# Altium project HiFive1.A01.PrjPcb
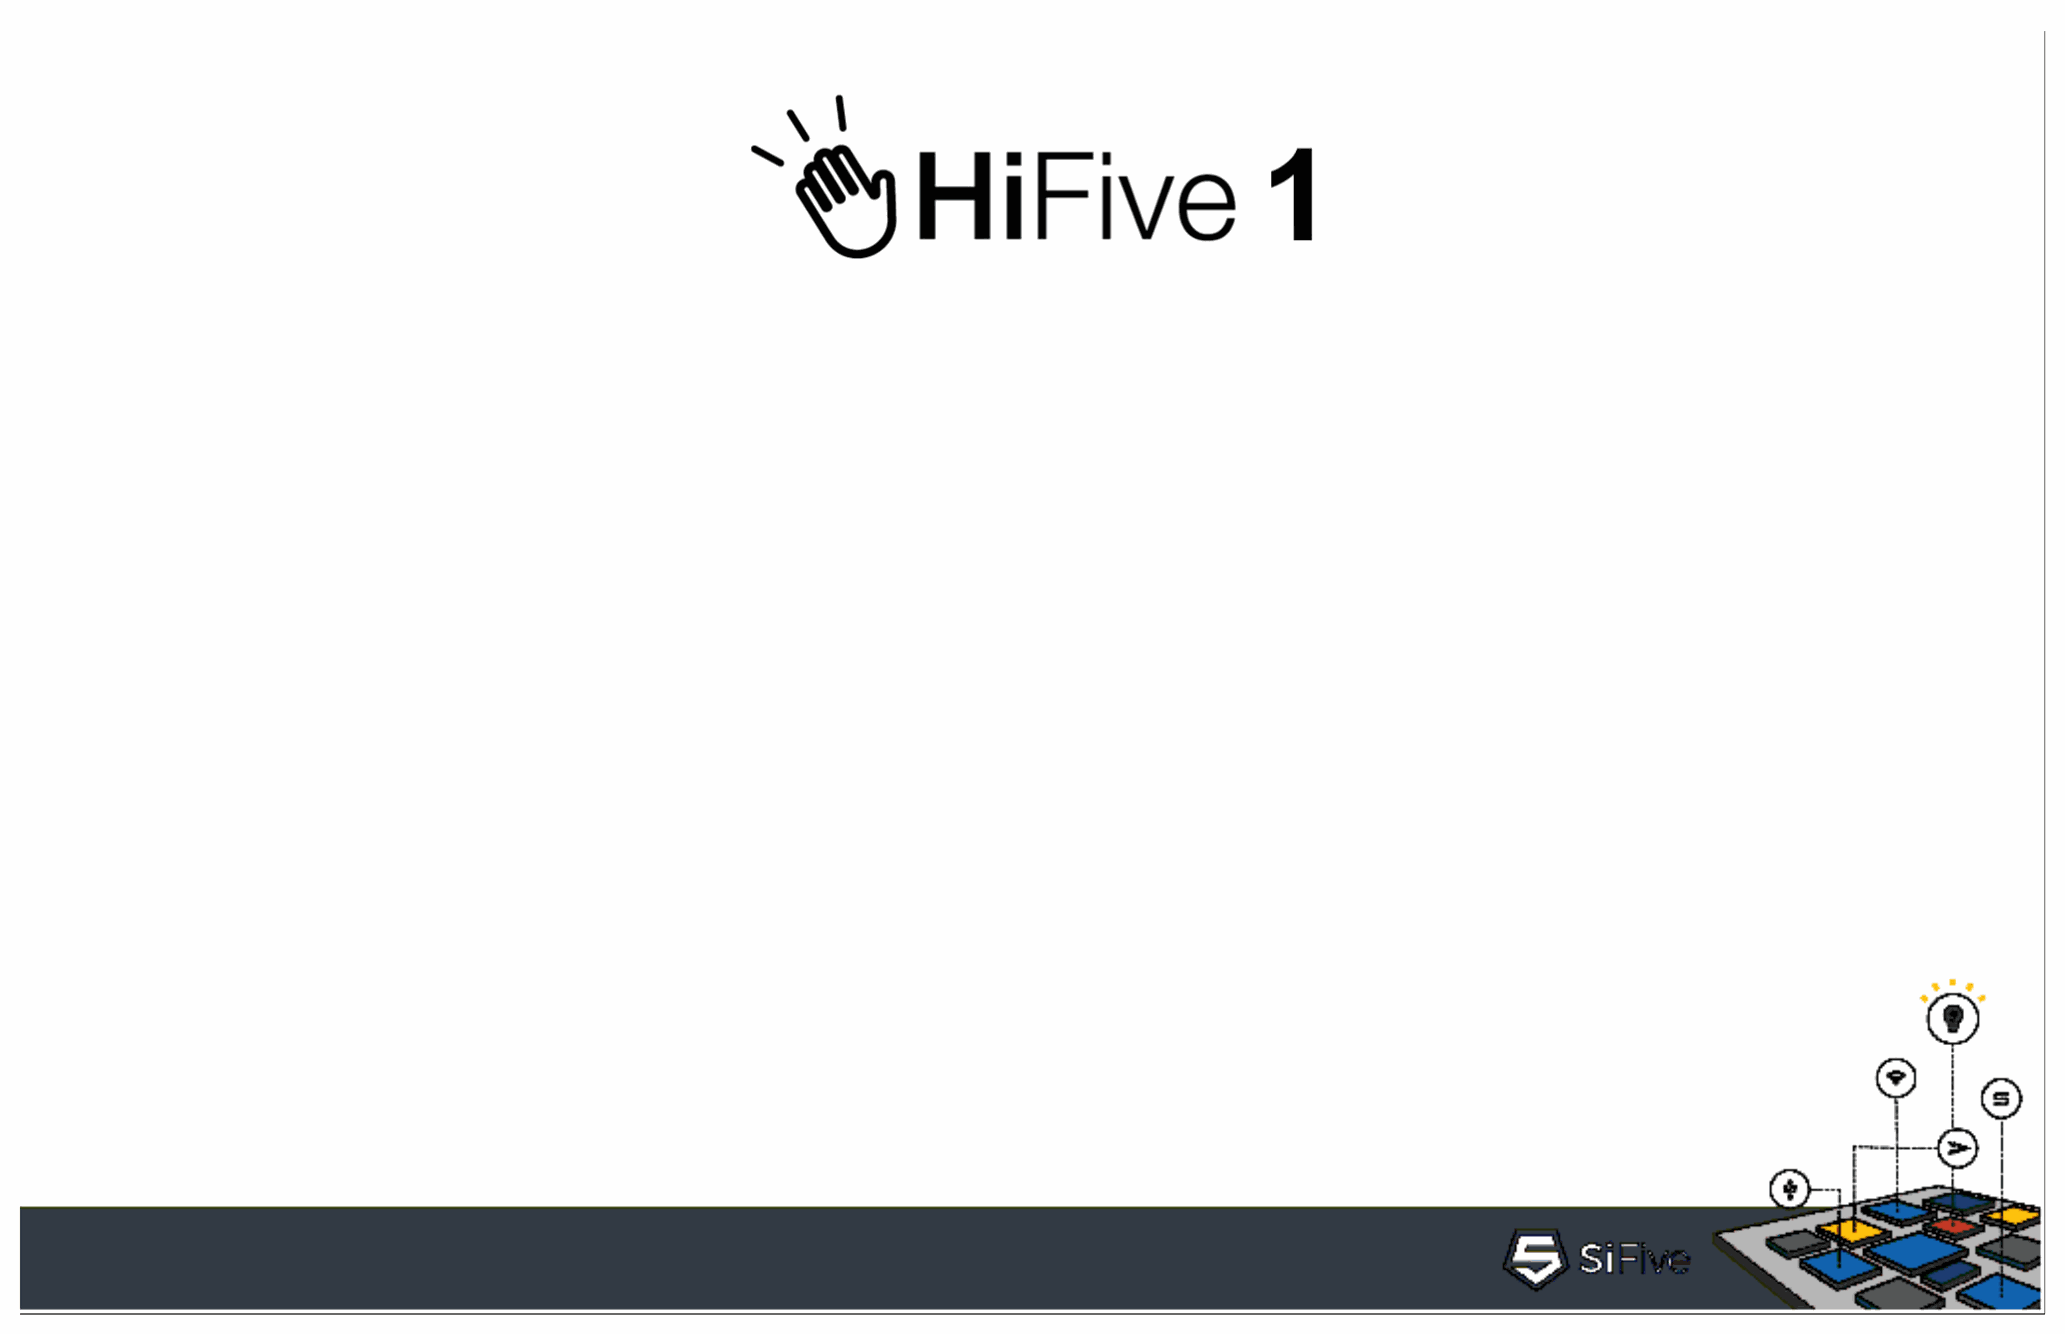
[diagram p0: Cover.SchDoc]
4 sheets, 123 parts. Net scope: flat (ports and power ports of the same name join across sheets).
Board file: HiFive1.A01.PcbDoc
Sheets:
  Cover.SchDoc
  Power.SchDoc
  Freedom_E310.SchDoc
  FT2232.SchDoc

## Sheet Cover.SchDoc
size B; SheetNumber: 1; SheetTotal: 4

## Sheet Power.SchDoc: Power Supply
size B; Revision: A01; SheetNumber: 2; SheetTotal: 4; ProjectCodeName: HiFive1
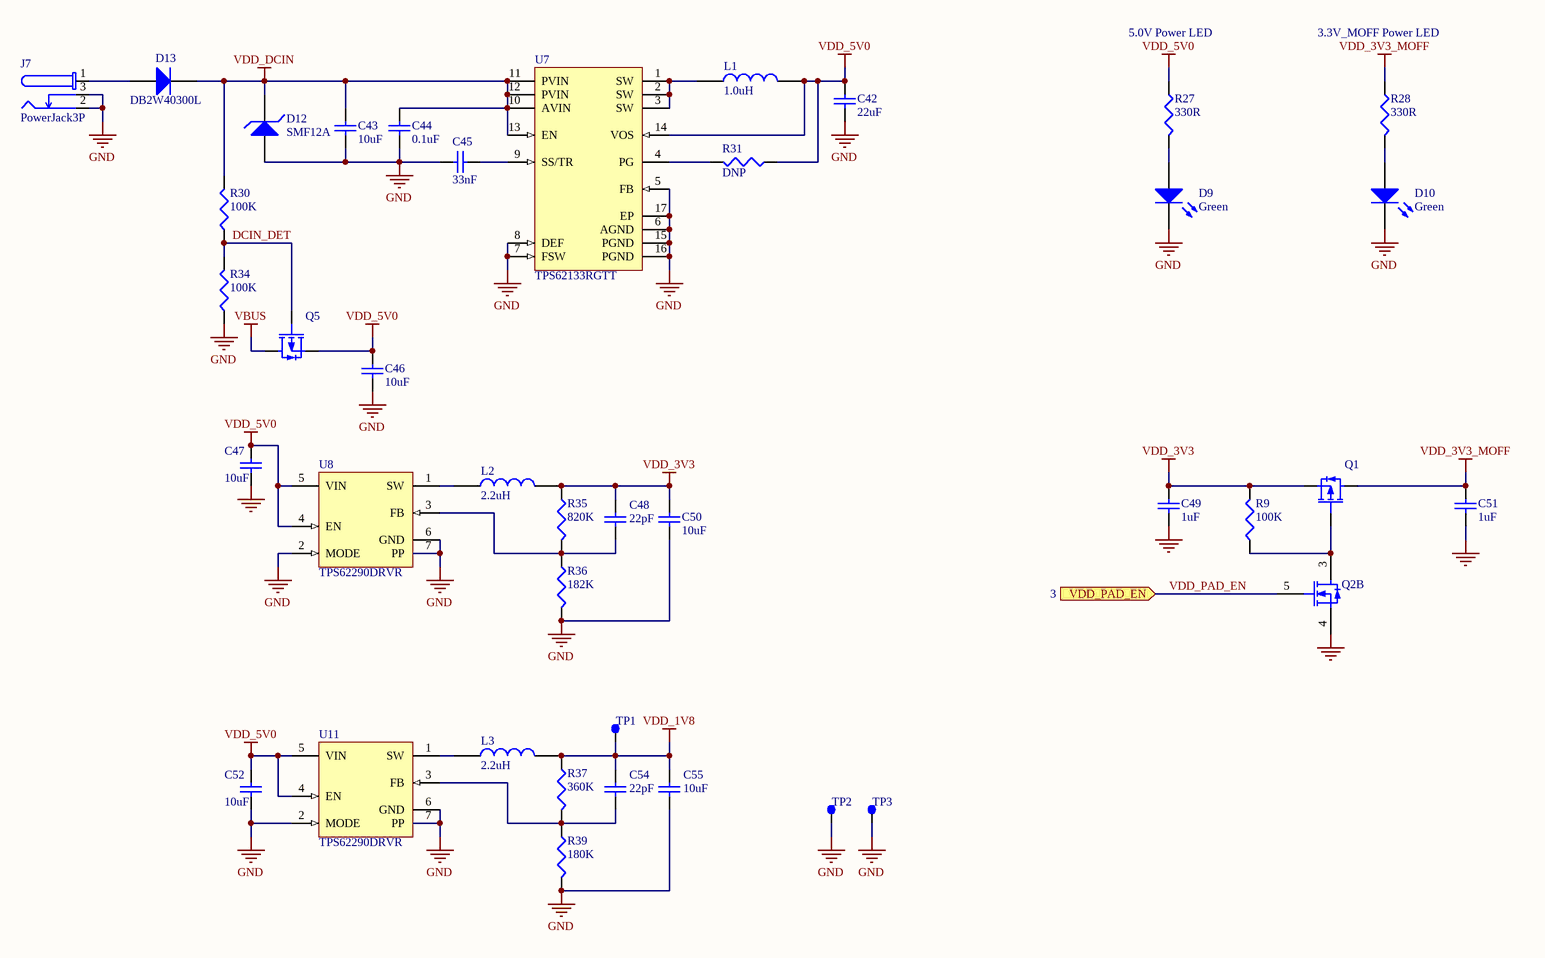
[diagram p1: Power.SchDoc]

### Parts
C42  22uF  [C0805]
C43  10uF  [C0805]
C44  0.1uF  [C0402]
C45  33nF  [C0402]
C46  10uF  [C0603]
C47  10uF  [C0603]
C48  22pF  [C0402]
C49  1uF  [C0603]
C50  10uF  [C0603]
C51  1uF  [C0603]
C52  10uF  [C0603]
C54  22pF  [C0402]
C55  10uF  [C0603]
D9  Green  [LED0805]
D10  Green  [LED0805]
D12  SMF12A  [SOD-123FL]
D13  DB2W40300L  [SOD-123FL]
J7  PowerJack3P  [PJ-102AH]
L1  1.0uH  [L252012]
L2  2.2uH  [L252012]
L3  2.2uH  [L252012]
Q1  MOSFET-P_SOT23  [SOT-23B]  (value not drawn)
Q2  DMN63D8LDW-7  [SC70-6]  (value not drawn)  (part B of 2)
Q5  MOSFET-P_SOT23  [SOT-23B]  (value not drawn)
R9  100K  [R0402]
R27  330R  [R0402]
R28  330R  [R0402]
R30  100K  [R0402]
R31  DNP  [R0402]  (no BOM)
R34  100K  [R0402]
R35  820K  [R0402]
R36  182K  [R0402]
R37  360K  [R0402]
R39  180K  [R0402]
TP1  Testpoint  [Testpoint_SMT]  (value not drawn)  (no BOM)
TP2  Testpoint  [Testpoint_SMT]  (value not drawn)  (no BOM)
TP3  Testpoint  [Testpoint_SMT]  (value not drawn)  (no BOM)
U7  TPS62133RGTT  [RGT16-1700X1700TP]
U8  TPS62290DRVR  [DRV6]
U11  TPS62290DRVR  [DRV6]

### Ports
VDD_PAD_EN (in, see 3)

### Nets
GND: C42.2 C43.2 C44.2 C45.2 C46.2 C47.2 C49.2 C50.2 C51.2 C52.2 C55.2 D9.1(K) D10.1(K) D12.2(A) J7.2 J7.3 Q2.4(S) R34.1 R36.2 R39.2 TP2.1 TP3.1 U7.5(FB) U7.6(AGND) U7.7(FSW) U7.8(DEF) U7.15(PGND) U7.16(PGND) U7.17(EP) U8.2(MODE) U8.6(GND) U8.7(PP) U11.2(MODE) U11.6(GND) U11.7(PP)
VBUS: Q5.3(D)
VDD_1V8: C54.1 C55.1 L3.2 R37.1 TP1.1
VDD_3V3: C48.1 C49.1 C50.1 L2.2 Q1.2(S) R9.2 R35.1
VDD_3V3_MOFF: C51.1 Q1.3(D) R28.1
VDD_5V0: C42.1 C46.1 C47.1 C52.1 L1.2 Q5.2(S) R27.1 R31.1 U7.14(VOS) U8.4(EN) U8.5(VIN) U11.4(EN) U11.5(VIN)
VDD_DCIN: C43.1 C44.1 D12.1(K) D13.1(K) R30.2 U7.10(AVIN) U7.11(PVIN) U7.12(PVIN) U7.13(EN)
DCIN_DET: Q5.1(G) R30.1 R34.2
VDD_PAD_EN: Q2.5(G) ; port VDD_PAD_EN
NetC45_1: C45.1 U7.9(SS/TR)
NetC48_2: C48.2 R35.2 R36.1 U8.3(FB)
NetC54_2: C54.2 R37.2 R39.1 U11.3(FB)
NetD9_2: D9.2(A) R27.2
NetD10_2: D10.2(A) R28.2
NetD13_2: D13.2(A) J7.1
NetL1_1: L1.1 U7.1(SW) U7.2(SW) U7.3(SW)
NetL2_1: L2.1 U8.1(SW)
NetL3_1: L3.1 U11.1(SW)
NetQ1_1: Q1.1(G) Q2.3(D) R9.1
NetR31_2: R31.2 U7.4(PG)

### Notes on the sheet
- 5.0V Power LED
- 3.3V_MOFF Power LED

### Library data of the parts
C42 = C0100010: 22µF 6.3V Ceramic Capacitor X5R 0805; Manufacturer: Murata Electronics; Manufacturer PN: GRM21BR60J226ME39L
C43 = C0100015: 10µF ±10% 25V Ceramic Capacitor X5R 0805; Manufacturer: Murata Electronics; Manufacturer PN: GRM21BR61E106KA73L
C44 = C0100004: 0.10µF 16V Ceramic Capacitor X7R 0402; Manufacturer: Murata Electronics; Manufacturer PN: GRM155R71C104KA88J
C45 = C0100011: 33nF 25V Ceramic Capacitor X7R 0402; Manufacturer: Murata Electronics; Manufacturer PN: GRM155R71E333KA88D
C46 C47 C50 C52 C55 = C0100007: 10µF 6.3V Ceramic Capacitor X5R 0603; Manufacturer: Murata Electronics; Manufacturer PN: GRM188R60J106ME47J
C48 C54 = C0100009: 22pF 50V Ceramic Capacitor C0G, NP0 0402; Manufacturer: Murata Electronics; Manufacturer PN: GRM1555C1H220JA01J
C49 C51 = C0100006: 1µF 16V Ceramic Capacitor X5R 0603; Manufacturer: Murata Electronics; Manufacturer PN: GRM188R61C105KA93D
D9 D10 = E0000001: Green 570nm LED Indication - Discrete 2.2V 0805; Manufacturer: OSRAM Opto Semiconductors Inc; Manufacturer PN: LG R971-KN-1
D12 = D0000002: TVS DIODE 12VWM 19.9VC SOD123; Manufacturer: Littelfuse Inc
D13 = D0000006: Diode Schottky 40V 3A (DC) Surface Mount; Manufacturer: Panasonic Electronic Components
J7 = J0000003: Power Barrel Connector Jack 2.00mm ID (0.079"), 5.50mm OD (0.217") Through Hole, Right Angle; Manufacturer: CUI Inc
L1 = L0000003: 1µH Shielded Inductor 3.3A 40 mOhm; Manufacturer: Murata Electronics; Manufacturer PN: DFE252012F-1R0M=P2
L2 L3 = L0000002: 2.2µH Shielded Wirewound Inductor 3A 84 mOhm; Manufacturer: Murata Electronics; Manufacturer PN: DFE252012P-2R2M=P2
Q1 Q5 = Q0000002: MOSFET P-CH 20V 3.7A SOT-23; Manufacturer: Infineon Technologies; Manufacturer PN: IRLML6402TRPBF; Value: P-Channel
Q2 = Q0000003: MOSFET 2N-CH 30V 0.22A SOT363; Manufacturer: Diodes Inc
R9 R30 R31 R34 = R0000012: RES SMD 100K OHM 1% 1/16W 0402; Manufacturer: Yageo; Manufacturer PN: RC0402FR-07100KL
R27 R28 = R0000026: RES SMD 330 OHM 1% 1/16W 0402; Manufacturer: Yageo; Manufacturer PN: RC0402FR-07330RL
R35 = R0000017: RES SMD 820K OHM 1% 1/16W 0402; Manufacturer: Yageo; Manufacturer PN: RC0402FR-07820KL
R36 = R0000018: RES SMD 182K OHM 1% 1/16W 0402; Manufacturer: Yageo; Manufacturer PN: RC0402FR-07182KL
R37 = R0000015: RES SMD 360K OHM 1% 1/16W 0402; Manufacturer: Yageo; Manufacturer PN: RC0402FR-07360KL
R39 = R0000014: RES SMD 180K OHM 1% 1/16W 0402; Manufacturer: Yageo; Manufacturer PN: RC0402FR-07180KL
TP1-TP3 = M0000002: Test Point SMT
U7 = U0000007: Buck Switching Regulator IC Positive Fixed 5V 1 Output 3A 16-VFQFN Exposed Pad; Manufacturer: Texas Instruments
U8 U11 = U0000006: Buck Switching Regulator IC Positive Adjustable 0.6V 1 Output 1A 6-WDFN Exposed Pad; Manufacturer: Texas Instruments

## Sheet Freedom_E310.SchDoc: Freedom E310
size B; Revision: A01; SheetNumber: 3; SheetTotal: 4; ProjectCodeName: HiFive1
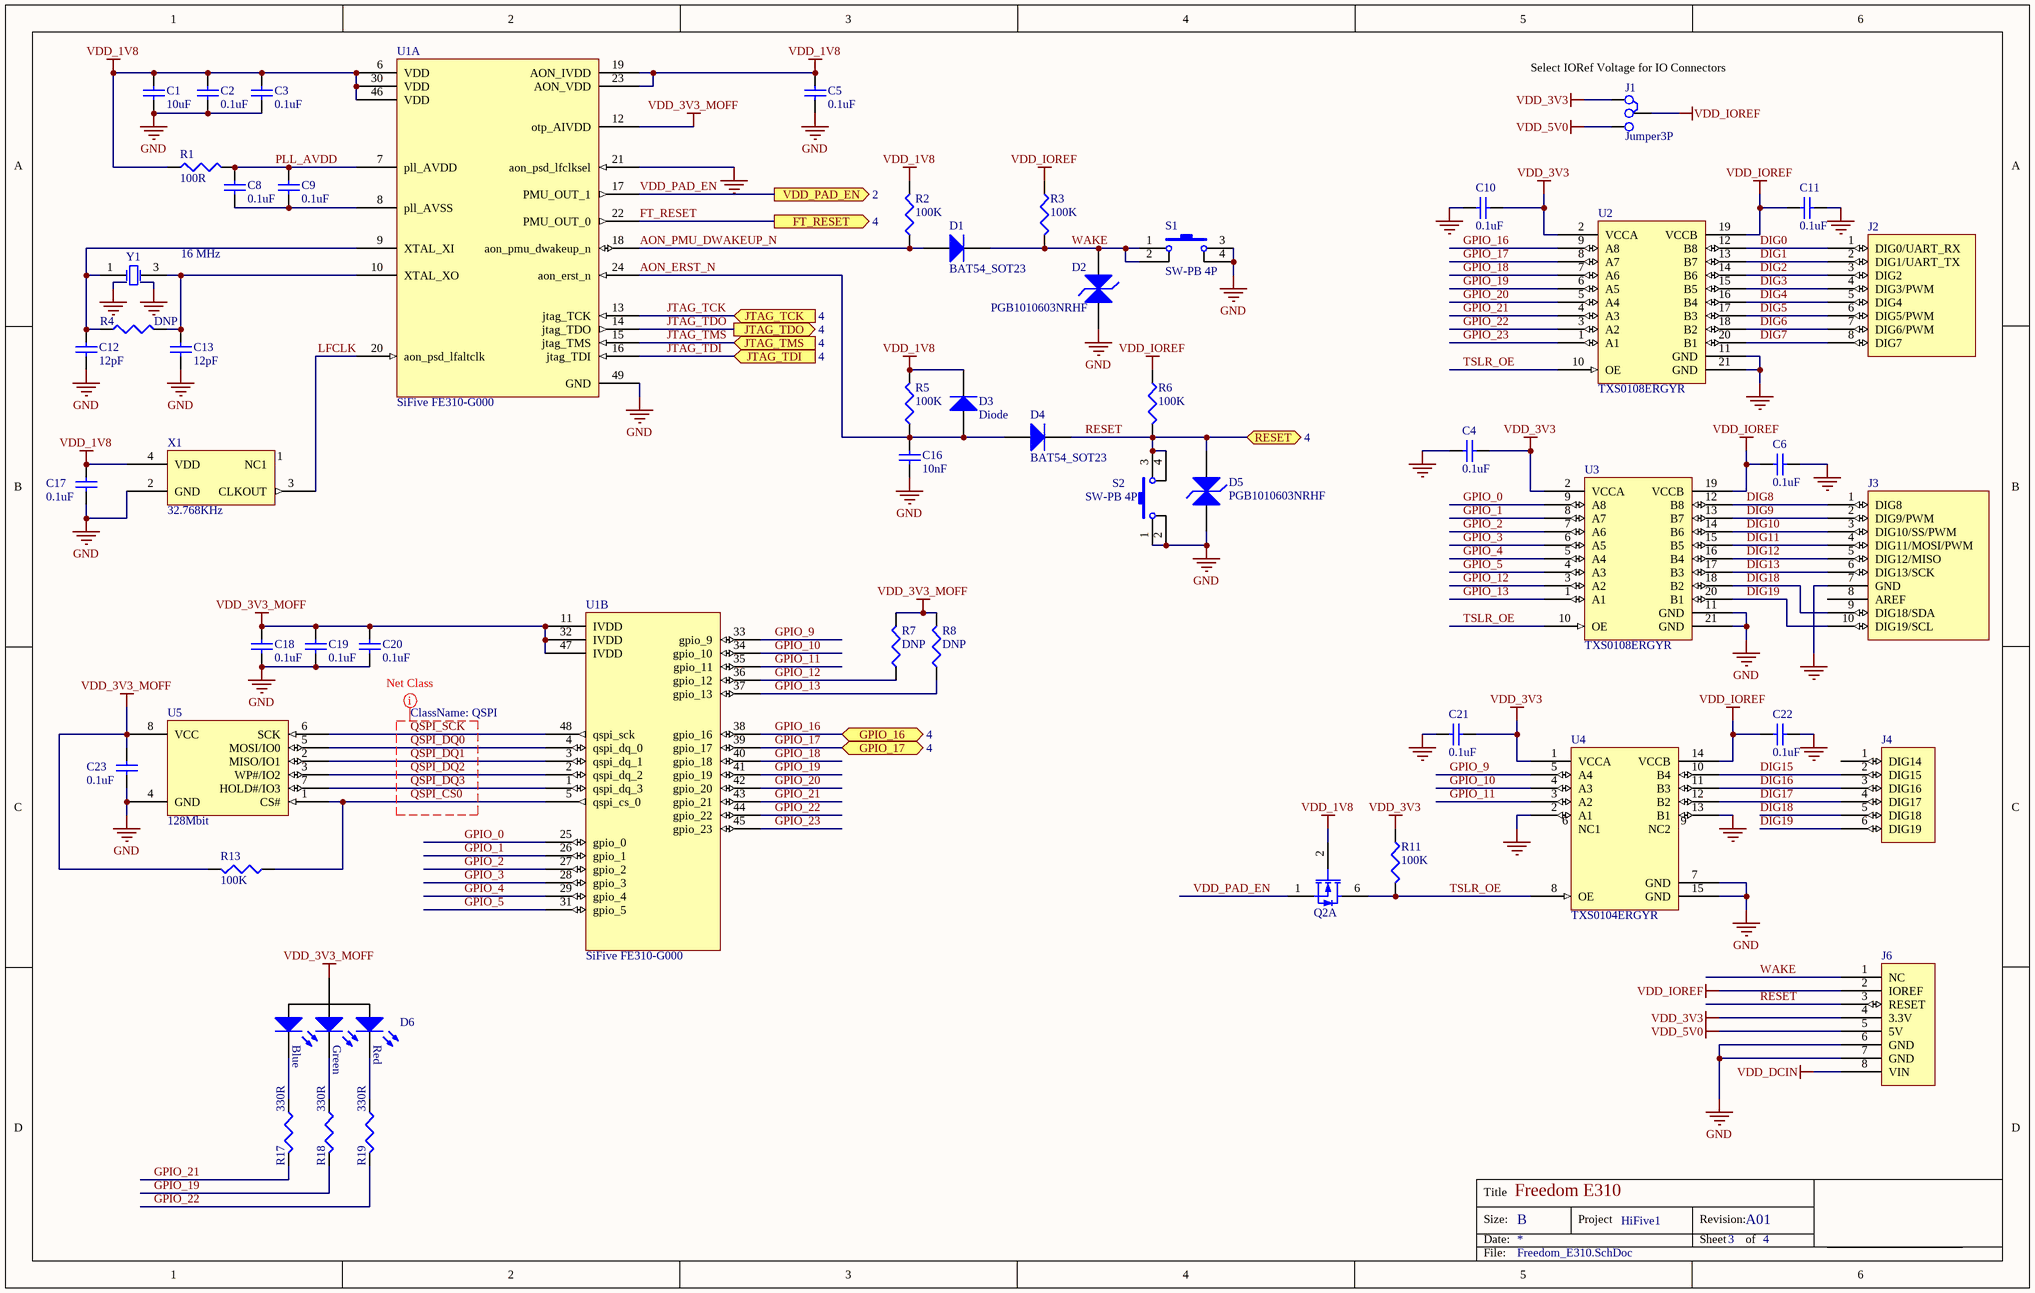
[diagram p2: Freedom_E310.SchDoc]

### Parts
C1  10uF  [C0603]
C2  0.1uF  [C0402]
C3  0.1uF  [C0402]
C4  0.1uF  [C0402]
C5  0.1uF  [C0402]
C6  0.1uF  [C0402]
C8  0.1uF  [C0402]
C9  0.1uF  [C0402]
C10  0.1uF  [C0402]
C11  0.1uF  [C0402]
C12  12pF  [C0402]
C13  12pF  [C0402]
C16  10nF  [C0402]
C17  0.1uF  [C0402]
C18  0.1uF  [C0402]
C19  0.1uF  [C0402]
C20  0.1uF  [C0402]
C21  0.1uF  [C0402]
C22  0.1uF  [C0402]
C23  0.1uF  [C0402]
D1  BAT54_SOT23  [SOT-23B]
D2  PGB1010603NRHF  [R0603]
D3  Diode  [SOD523]
D4  BAT54_SOT23  [SOT-23B]
D5  PGB1010603NRHF  [R0603]
D6  LED_RGB_LTST-C19HE1WT  [LED0606]  (value not drawn)
J1  Jumper3P  [Header_2.54mm_3p]
J2  8P_IO  [8P_IO]  (value not drawn)
J3  10P  [10P]  (value not drawn)
J4  6P  [6P]  (value not drawn)
J6  POWER  [8P_POWER]  (value not drawn)
Q2  DMN63D8LDW-7  [SC70-6]  (value not drawn)  (part A of 2)
R1  100R  [R0402]
R2  100K  [R0402]
R3  100K  [R0402]
R4  DNP  [R0402]  (no BOM)
R5  100K  [R0402]
R6  100K  [R0402]
R7  DNP  [R0402]  (no BOM)
R8  DNP  [R0402]  (no BOM)
R11  100K  [R0402]
R13  100K  [R0402]
R17  330R  [R0402]
R18  330R  [R0402]
R19  330R  [R0402]
S1  SW-PB 4P  [PTS645_SMT]
S2  SW-PB 4P  [PTS645_SMT]
U1  SiFive FE310-G000  [QFN48_40P600X600X90_HS-49]  (parts A,B of 2)
U2  TXS0108ERGYR  [RGY-20]
U3  TXS0108ERGYR  [RGY-20]
U4  TXS0104ERGYR  [RGY-14]
U5  128Mbit  [SOIC127P790X216-8N]
X1  32.768KHz  [SiTime2012]
Y1  16 MHz  [X3225]

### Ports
FT_RESET (out, see 4), GPIO_16 (bidir, see 4), GPIO_17 (bidir, see 4), JTAG_TCK (in, see 4), JTAG_TDI (in, see 4), JTAG_TDO (out, see 4), JTAG_TMS (in, see 4), RESET (bidir, see 4), VDD_PAD_EN (out, see 2)

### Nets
GND: C1.2 C2.2 C3.2 C4.2 C5.2 C6.2 C10.2 C11.2 C12.2 C13.2 C16.2 C17.2 C18.2 C19.2 C20.2 C21.2 C22.2 C23.2 D2.2 D5.2 J3.7(GND) J6.6(GND) J6.7(GND) S1.3 S1.4 S2.1 S2.2 U1.21(aon_psd_lfclksel) U1.49(GND) U2.11(GND) U2.21(GND) U3.11(GND) U3.21(GND) U4.2(A1) U4.7(GND) U4.13(B1) U4.15(GND) U5.4(GND) X1.2(GND) Y1.2(NC1) Y1.4(NC2)
VDD_1V8: C1.1 C2.1 C3.1 C5.1 C17.1 D3.1(K) Q2.2(G) R1.1 R2.2 R5.2 U1.6(VDD) U1.19(AON_IVDD) U1.23(AON_VDD) U1.30(VDD) U1.46(VDD) X1.4(VDD)
VDD_3V3: C4.1 C10.1 C21.1 J1.1(C1) J6.4(3.3V) R11.1 U2.2(VCCA) U3.2(VCCA) U4.1(VCCA)
VDD_3V3_MOFF: C18.1 C19.1 C20.1 C23.1 D6.4(A) R7.2 R8.2 R13.2 U1.11(IVDD) U1.12(otp_AIVDD) U1.32(IVDD) U1.47(IVDD) U5.8(VCC)
VDD_5V0: J1.3(C3) J6.5(5V)
VDD_DCIN: J6.8(VIN)
VDD_IOREF: C6.1 C11.1 C22.1 J1.2(C2) J6.2(IOREF) R3.1 R6.1 U2.19(VCCB) U3.19(VCCB) U4.14(VCCB)
AON_ERST_N: C16.1 D3.2(A) D4.1(A) R5.1 U1.24(aon_erst_n)
AON_PMU_DWAKEUP_N: D1.1(A) R2.1 U1.18(aon_pmu_dwakeup_n)
DIG0: J2.1(DIG0/UART_RX) U2.12(B8)
DIG1: J2.2(DIG1/UART_TX) U2.13(B7)
DIG2: J2.3(DIG2) U2.14(B6)
DIG3: J2.4(DIG3/PWM) U2.15(B5)
DIG4: J2.5(DIG4) U2.16(B4)
DIG5: J2.6(DIG5/PWM) U2.17(B3)
DIG6: J2.7(DIG6/PWM) U2.18(B2)
DIG7: J2.8(DIG7) U2.20(B1)
DIG8: J3.1(DIG8) U3.12(B8)
DIG9: J3.2(DIG9/PWM) U3.13(B7)
DIG10: J3.3(DIG10/SS/PWM) U3.14(B6)
DIG11: J3.4(DIG11/MOSI/PWM) U3.15(B5)
DIG12: J3.5(DIG12/MISO) U3.16(B4)
DIG13: J3.6(DIG13/SCK) U3.17(B3)
DIG15: J4.2(DIG15) U4.10(B4)
DIG16: J4.3(DIG16) U4.11(B3)
DIG17: J4.4(DIG17) U4.12(B2)
DIG18: J3.9(DIG18/SDA) J4.5(DIG18) U3.18(B2)
DIG19: J3.10(DIG19/SCL) J4.6(DIG19) U3.20(B1)
FT_RESET: U1.22(PMU_OUT_0) ; port FT_RESET
GPIO_0: U1.25(gpio_0) U3.9(A8)
GPIO_1: U1.26(gpio_1) U3.8(A7)
GPIO_2: U1.27(gpio_2) U3.7(A6)
GPIO_3: U1.28(gpio_3) U3.6(A5)
GPIO_4: U1.29(gpio_4) U3.5(A4)
GPIO_5: U1.31(gpio_5) U3.4(A3)
GPIO_9: U1.33(gpio_9) U4.5(A4)
GPIO_10: U1.34(gpio_10) U4.4(A3)
GPIO_11: U1.35(gpio_11) U4.3(A2)
GPIO_12: R7.1 U1.36(gpio_12) U3.3(A2)
GPIO_13: R8.1 U1.37(gpio_13) U3.1(A1)
GPIO_16: U1.38(gpio_16) U2.9(A8) ; port GPIO_16
GPIO_17: U1.39(gpio_17) U2.8(A7) ; port GPIO_17
GPIO_18: U1.40(gpio_18) U2.7(A6)
GPIO_19: R18.2 U1.41(gpio_19) U2.6(A5)
GPIO_20: U1.42(gpio_20) U2.5(A4)
GPIO_21: R17.2 U1.43(gpio_21) U2.4(A3)
GPIO_22: R19.2 U1.44(gpio_22) U2.3(A2)
GPIO_23: U1.45(gpio_23) U2.1(A1)
JTAG_TCK: U1.13(jtag_TCK) ; port JTAG_TCK
JTAG_TDI: U1.16(jtag_TDI) ; port JTAG_TDI
JTAG_TDO: U1.14(jtag_TDO) ; port JTAG_TDO
JTAG_TMS: U1.15(jtag_TMS) ; port JTAG_TMS
LFCLK: U1.20(aon_psd_lfaltclk) X1.3(CLKOUT)
PLL_AVDD: C8.1 C9.1 R1.2 U1.7(pll_AVDD)
QSPI_CS0: R13.1 U1.5(qspi_cs_0) U5.1(CS#)
QSPI_DQ0: U1.4(qspi_dq_0) U5.5(MOSI/IO0)
QSPI_DQ1: U1.3(qspi_dq_1) U5.2(MISO/IO1)
QSPI_DQ2: U1.2(qspi_dq_2) U5.3(WP#/IO2)
QSPI_DQ3: U1.1(qspi_dq_3) U5.7(HOLD#/IO3)
QSPI_SCK: U1.48(qspi_sck) U5.6(SCK)
RESET: D4.3(K) D5.1 J6.3(RESET) R6.2 S2.3 S2.4 ; port RESET
TSLR_OE: Q2.6(D) R11.2 U2.10(OE) U3.10(OE) U4.8(OE)
VDD_PAD_EN: Q2.1(S) U1.17(PMU_OUT_1) ; port VDD_PAD_EN
WAKE: D1.3(K) D2.1 J6.1(NC) R3.2 S1.1 S1.2
NetC8_2: C8.2 C9.2 U1.8(pll_AVSS)
NetC12_1: C12.1 R4.1 U1.9(XTAL_XI) Y1.1(OSC1)
NetC13_1: C13.1 R4.2 U1.10(XTAL_XO) Y1.3(OSC2)
NetD6_1: D6.1(RedK) R19.1
NetD6_2: D6.2(GreenK) R18.1
NetD6_3: D6.3(BlueK) R17.1

Not connected (* = marked no-connect by the designer): D1 2(NC); D4 2(NC); J3 8(AREF); J4 1(DIG14); U4 6(NC1) 9(NC2); X1 1(NC1)

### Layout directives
net class QSPI: QSPI_CS0, QSPI_DQ0, QSPI_DQ1, QSPI_DQ2, QSPI_DQ3, QSPI_SCK

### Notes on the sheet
- (near J1) Select IORef Voltage for IO Connectors

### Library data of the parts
C1 = C0100007: as C46 on sheet Power
C2-C6 C8-C11 C17-C23 = C0100004: as C44 on sheet Power
C12 C13 = C0100012: CAP CER 12PF 50V NP0 0402; Manufacturer: Murata Electronics; Manufacturer PN: GRM1555C1H120JA01D
C16 = C0100014: 10nF 50V Ceramic Capacitor X5R 0402; Manufacturer: Murata Electronics; Manufacturer PN: GRM155R71H103KA88D
D1 D4 = D0000004: Diode Schottky 30V 200mA Surface Mount SOT-23-3 (TO-236); Manufacturer: Fairchild Semiconductor; Value: BAT54
D2 D5 = D0000003: TVS DIODE 24VWM 150VC 0603; Manufacturer: Littelfuse Inc
D3 = D0000001: Diode Standard 80V 125mA Surface Mount SOD-523; Manufacturer: Diodes Incorporated; Value: 1N4148WT-7
D6 = E0000005: Red, Green, Blue (RGB) 624nm Red, 525nm Green, 470nm Blue LED Indication - Discrete 1.8V Red, 2.8V Green, 2.8V Blue 0606; Manufacturer: Lite-on Inc.
J1 = J0000014: 3 Positions Header, Unshrouded, Breakaway Connector 0.100" (2.54mm) Through Hole Tin; Manufacturer: Harwin Inc; Manufacturer PN: M20-9770346
J2 = 8P_IO: 8 Pin I/O Connector; Manufacturer: Sullins Connector Solutions; Manufacturer PN: PPTC081LFBN-RC
J3 = 10P: 10 Pin Connector; Manufacturer: Sullins Connector Solutions; Manufacturer PN: PPTC101LFBN-RC
J4 = 6P: Connector; Manufacturer: Sullins Connector Solutions; Manufacturer PN: PPTC061LFBN-RC
J6 = 8P_POWER: Power Connector; Manufacturer: Sullins Connector Solutions; Manufacturer PN: PPTC081LFBN-RC
Q2 = Q0000003: as Q2 on sheet Power
R1 = R0000020: RES SMD 100 OHM 1% 1/16W 0402; Manufacturer: Yageo; Manufacturer PN: RC0402FR-07100RL
R2 R3 R5 R6 R11 R13 = R0000012: as R9 on sheet Power
R4 = R0000021: RES SMD 1M OHM 1% 1/16W 0402; Manufacturer: Yageo; Manufacturer PN: RC0402FR-071ML
R7 R8 = R0000025: RES SMD 2K OHM 1% 1/16W 0402; Manufacturer: Yageo; Manufacturer PN: RC0402FR-072KL
R17-R19 = R0000026: as R27 on sheet Power
S1 = M0000004: Blue Tactile Switch SPST-NO Top Actuated Surface Mount; Manufacturer: C & K Components; Manufacturer PN: PTS645SM43SMTR92 LFS
S2 = M0000003: Red Tactile Switch SPST-NO Top Actuated Surface Mount; Manufacturer: C & K Components; Manufacturer PN: PTS645SK43SMTR92 LFS
U1 = Freedom-E310: Manufacturer PN: FE310-G000-A01
U2 U3 = U0000010: Voltage Level Translator Bidirectional 1 Circuit 8 Channel 60Mbps 20-VQFN (3.5x4.5); Manufacturer: Texas Instruments
U4 = U0000009: Voltage Level Translator Bidirectional 1 Circuit 4 Channel 24Mbps 14-VQFN (3.5x3.5); Manufacturer: Texas Instruments
U5 = U0000011: IC FLASH 128MBIT 133MHZ 8SOIC; Manufacturer: ISSI; Manufacturer PN: IS25LP128-JBLE
X1 = X0000003: 32.768kHz LVCMOS MEMS (Silicon) Oscillator Surface Mount 1.2 V ~ 3.63 V 1.3µA; Manufacturer: SiTime; Manufacturer PN: SIT1533AC-H5-D14-32.768D
Y1 = X0000002: 16MHz ±30ppm Crystal 12pF 80 Ohm; Manufacturer: TXC Corporation; Manufacturer PN: 7M-16.000MAAE-T

## Sheet FT2232.SchDoc: USB to UART and JTAG
size B; Revision: A01; SheetNumber: 4; SheetTotal: 4; ProjectCodeName: HiFive1
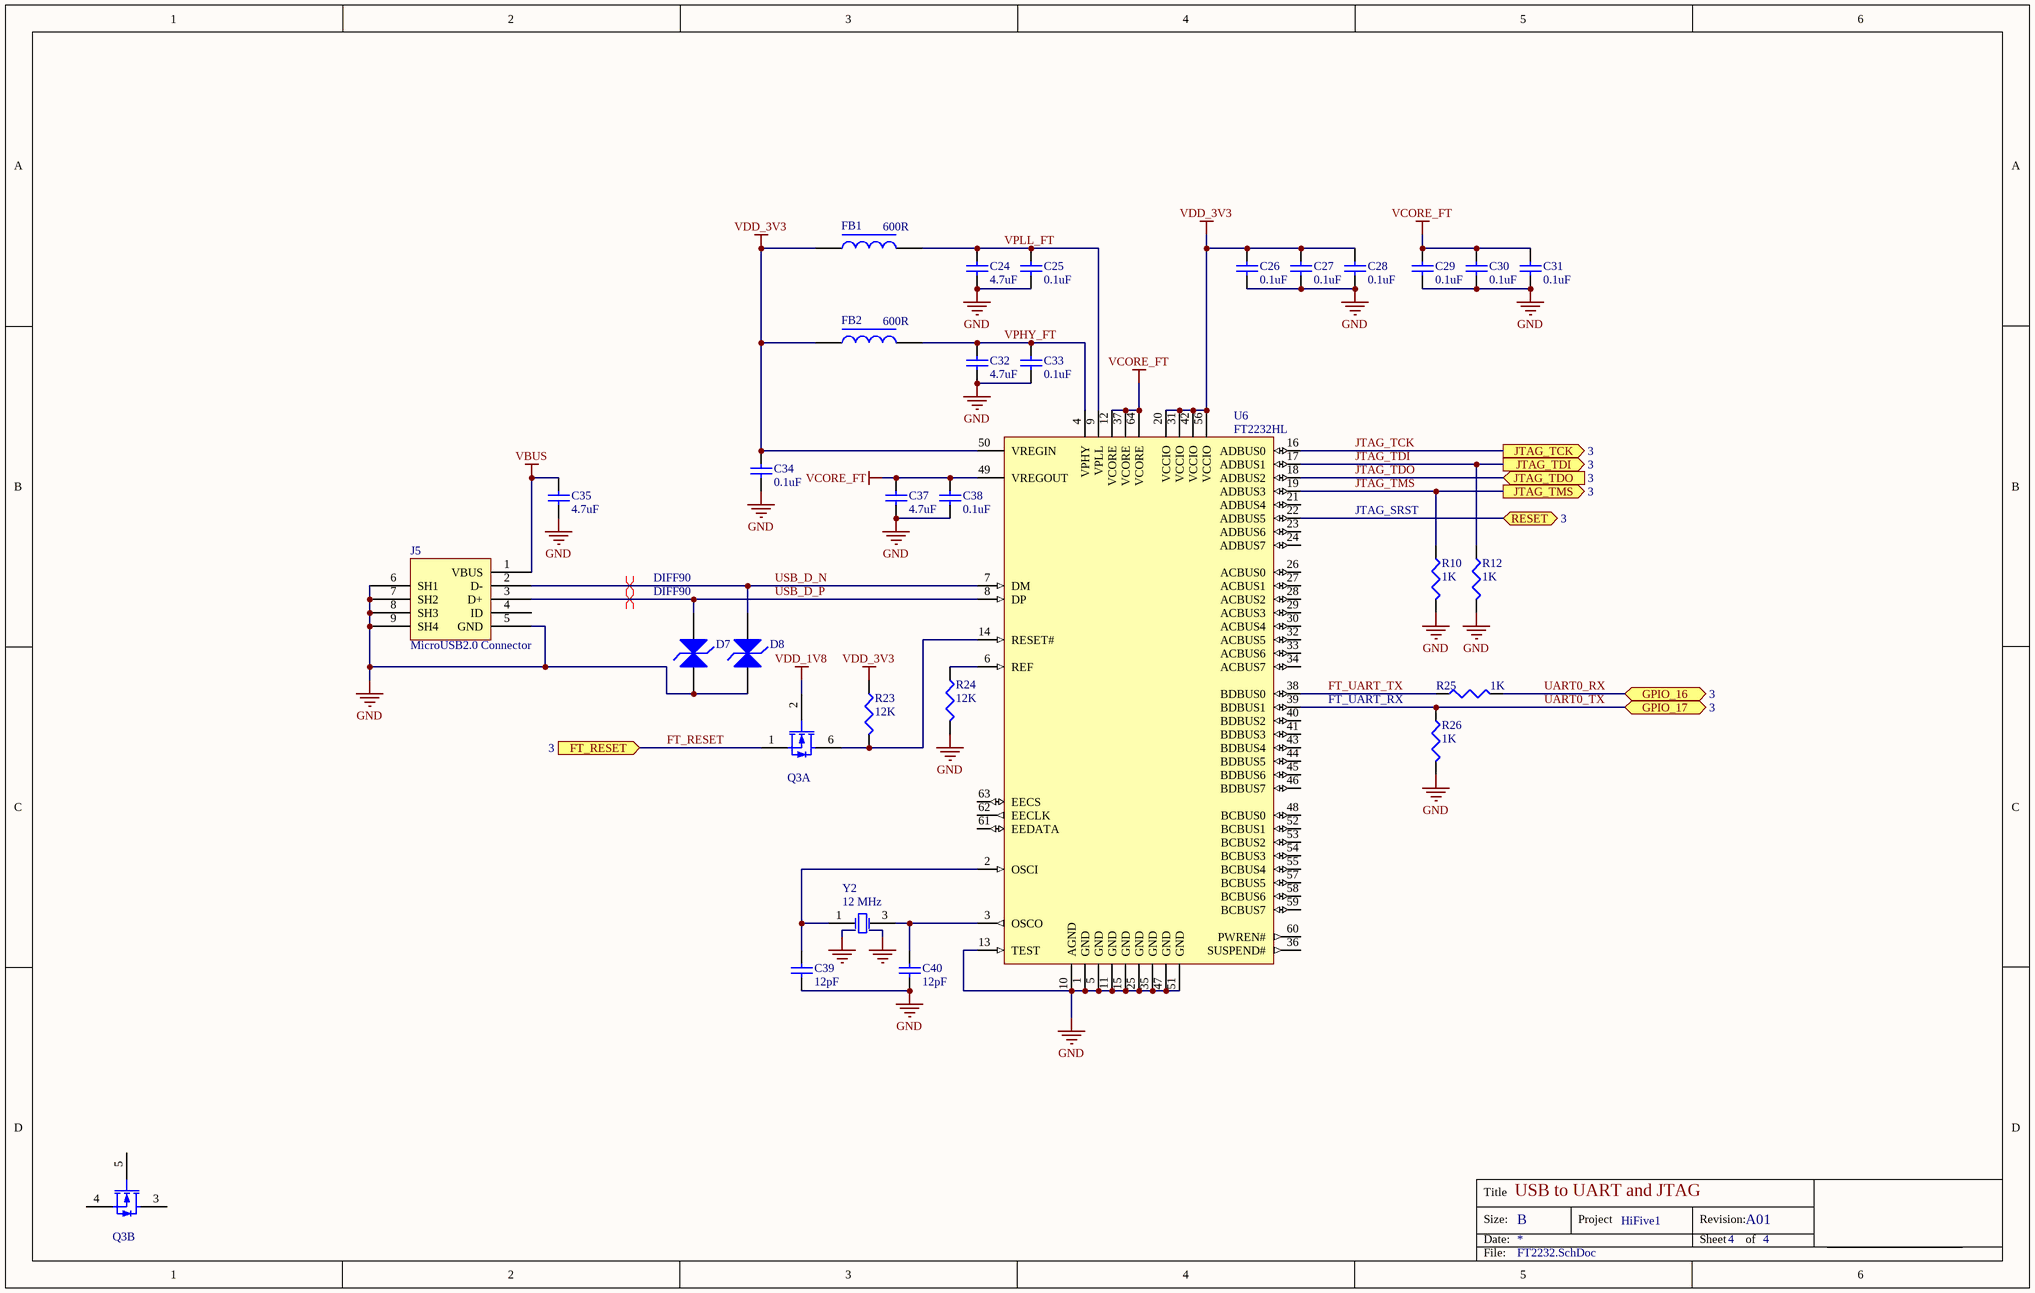
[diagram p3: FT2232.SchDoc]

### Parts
C24  4.7uF  [C0805]
C25  0.1uF  [C0402]
C26  0.1uF  [C0402]
C27  0.1uF  [C0402]
C28  0.1uF  [C0402]
C29  0.1uF  [C0402]
C30  0.1uF  [C0402]
C31  0.1uF  [C0402]
C32  4.7uF  [C0805]
C33  0.1uF  [C0402]
C34  0.1uF  [C0402]
C35  4.7uF  [C0805]
C37  4.7uF  [C0805]
C38  0.1uF  [C0402]
C39  12pF  [C0402]
C40  12pF  [C0402]
D7  PGB1010603NRHF  [R0603]  (value not drawn)
D8  PGB1010603NRHF  [R0603]  (value not drawn)
FB1  600R  [R0805]
FB2  600R  [R0805]
J5  MicroUSB2.0 Connector  [UJ2-MIBH2-4-SMT]
Q3  DMN63D8LDW-7  [SC70-6]  (value not drawn)  (parts A,B of 2)
R10  1K  [R0402]
R12  1K  [R0402]
R23  12K  [R0402]
R24  12K  [R0402]
R25  1K  [R0402]
R26  1K  [R0402]
U6  FT2232HL  [LQFP-64]
Y2  12 MHz  [X3225]

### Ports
FT_RESET (in, see 3), GPIO_16 (bidir, see 3), GPIO_17 (bidir, see 3), JTAG_TCK (out, see 3), JTAG_TDI (out, see 3), JTAG_TDO (in, see 3), JTAG_TMS (out, see 3), RESET (bidir, see 3)

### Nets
GND: C24.2 C25.2 C26.2 C27.2 C28.2 C29.2 C30.2 C31.2 C32.2 C33.2 C34.2 C35.2 C37.2 C38.2 C39.2 C40.2 D7.2 D8.2 J5.5(GND) J5.6(SH1) J5.7(SH2) J5.8(SH3) J5.9(SH4) R10.2 R12.2 R24.2 R26.2 U6.1(GND) U6.5(GND) U6.10(AGND) U6.11(GND) U6.13(TEST) U6.15(GND) U6.25(GND) U6.35(GND) U6.47(GND) U6.51(GND) Y2.2(NC1) Y2.4(NC2)
VBUS: C35.1 J5.1(VBUS)
VCORE_FT: C29.1 C30.1 C31.1 C37.1 C38.1 U6.12(VCORE) U6.37(VCORE) U6.49(VREGOUT) U6.64(VCORE)
VDD_1V8: Q3.2(G)
VDD_3V3: C26.1 C27.1 C28.1 C34.1 FB1.1 FB2.1 R23.1 U6.20(VCCIO) U6.31(VCCIO) U6.42(VCCIO) U6.50(VREGIN) U6.56(VCCIO)
FT_RESET: Q3.1(S) ; port FT_RESET
FT_UART_TX: R25.1 U6.38(BDBUS0)
JTAG_TCK: U6.16(ADBUS0) ; port JTAG_TCK
JTAG_TDI: R12.1 U6.17(ADBUS1) ; port JTAG_TDI
JTAG_TDO: U6.18(ADBUS2) ; port JTAG_TDO
JTAG_TMS: R10.1 U6.19(ADBUS3) ; port JTAG_TMS
RESET: U6.22(ADBUS5) ; port RESET
UART0_RX: R25.2 ; port GPIO_16  [project net GPIO_16]
UART0_TX: R26.1 U6.39(BDBUS1) ; port GPIO_17  [project net GPIO_17]
USB_D_N: D8.1 J5.2(D-) U6.7(DM)
USB_D_P: D7.1 J5.3(D+) U6.8(DP)
VPHY_FT: C32.1 C33.1 FB2.2 U6.4(VPHY)
VPLL_FT: C24.1 C25.1 FB1.2 U6.9(VPLL)
NetC39_1: C39.1 U6.2(OSCI) Y2.1(OSC1)
NetC40_1: C40.1 U6.3(OSCO) Y2.3(OSC2)
NetQ3_6: Q3.6(D) R23.2 U6.14(RESET#)
NetR24_1: R24.1 U6.6(REF)

Not connected (* = marked no-connect by the designer): J5 4(ID); Q3 3(D) 4(S) 5(G); U6 21(ADBUS4) 23(ADBUS6) 24(ADBUS7) 26(ACBUS0) 27(ACBUS1) 28(ACBUS2) 29(ACBUS3) 30(ACBUS4) 32(ACBUS5) 33(ACBUS6) 34(ACBUS7) 36(SUSPEND#) 40(BDBUS2) 41(BDBUS3) 43(BDBUS4) 44(BDBUS5) 45(BDBUS6) 46(BDBUS7) 48(BCBUS0) 52(BCBUS1) 53(BCBUS2) 54(BCBUS3) 55(BCBUS4) 57(BCBUS5) 58(BCBUS6) 59(BCBUS7) 60(PWREN#) 61(EEDATA) 62(EECLK) 63(EECS)

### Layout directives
differential pair; net class DIFF90: USB_D_N, USB_D_P

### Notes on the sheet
- (near R10) JTAG_SRST
- FT_UART_RX

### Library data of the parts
C24 C32 C35 C37 = C0100013: 4.7µF 16V Ceramic Capacitor X5R 0805; Manufacturer: Murata Electronics; Manufacturer PN: GRM21BR61C475KA88L
C25-C31 C33 C34 C38 = C0100004: as C44 on sheet Power
C39 C40 = C0100012: as C12 on sheet Freedom_E310
D7 D8 = D0000003: as D2 on sheet Freedom_E310
FB1 FB2 = F0000001: FERRITE BEAD 600 OHM 0805; Manufacturer: Laird-Signal Integrity Products; Manufacturer PN: HZ0805E601R-10
J5 = MicroUSB2.0 Connector: USB - micro B USB 2.0 Receptacle Connector 5 Position Surface Mount, Right Angle, Horizontal; Manufacturer: CUI Inc
Q3 = Q0000003: as Q2 on sheet Power
R10 R12 R25 R26 = R0000019: RES SMD 1K OHM 1% 1/16W 0402; Manufacturer: Yageo; Manufacturer PN: RC0402FR-071KL
R23 R24 = R0000023: RES SMD 12K OHM 1% 1/16W 0402; Manufacturer: Yageo; Manufacturer PN: RC0402FR-0712KL
U6 = U0000001: IC USB Bridge, USB to UART,FIFO USB 2.0 UART Interface 64-LQFP; Manufacturer: FTDI; Manufacturer PN: FT2232HL-REEL
Y2 = X0000004: 12MHz ±30ppm Crystal 10pF 120 Ohm -20°C ~ 70°C; Manufacturer: Abracon LLC; Manufacturer PN: ABM8G-12.000MHZ-B4Y-T

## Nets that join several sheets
GND: Power (35 pins), Freedom_E310 (41 pins), FT2232 (39 pins)
VBUS: Power (Q5.3), FT2232 (C35.1 J5.1)
VDD_1V8: Power (5 pins), Freedom_E310 (16 pins), FT2232 (Q3.2)
VDD_3V3: Power (7 pins), Freedom_E310 (9 pins), FT2232 (12 pins)
VDD_3V3_MOFF: Power (C51.1 Q1.3 R28.1), Freedom_E310 (13 pins)
VDD_5V0: Power (13 pins), Freedom_E310 (J1.3 J6.5)
VDD_DCIN: Power (9 pins), Freedom_E310 (J6.8)
FT_RESET: Freedom_E310 (U1.22), FT2232 (Q3.1)
GPIO_16: Freedom_E310 (U1.38 U2.9), FT2232 (R25.2)
GPIO_17: Freedom_E310 (U1.39 U2.8), FT2232 (R26.1 U6.39)
JTAG_TCK: Freedom_E310 (U1.13), FT2232 (U6.16)
JTAG_TDI: Freedom_E310 (U1.16), FT2232 (R12.1 U6.17)
JTAG_TDO: Freedom_E310 (U1.14), FT2232 (U6.18)
JTAG_TMS: Freedom_E310 (U1.15), FT2232 (R10.1 U6.19)
RESET: Freedom_E310 (6 pins), FT2232 (U6.22)
VDD_PAD_EN: Power (Q2.5), Freedom_E310 (Q2.1 U1.17)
